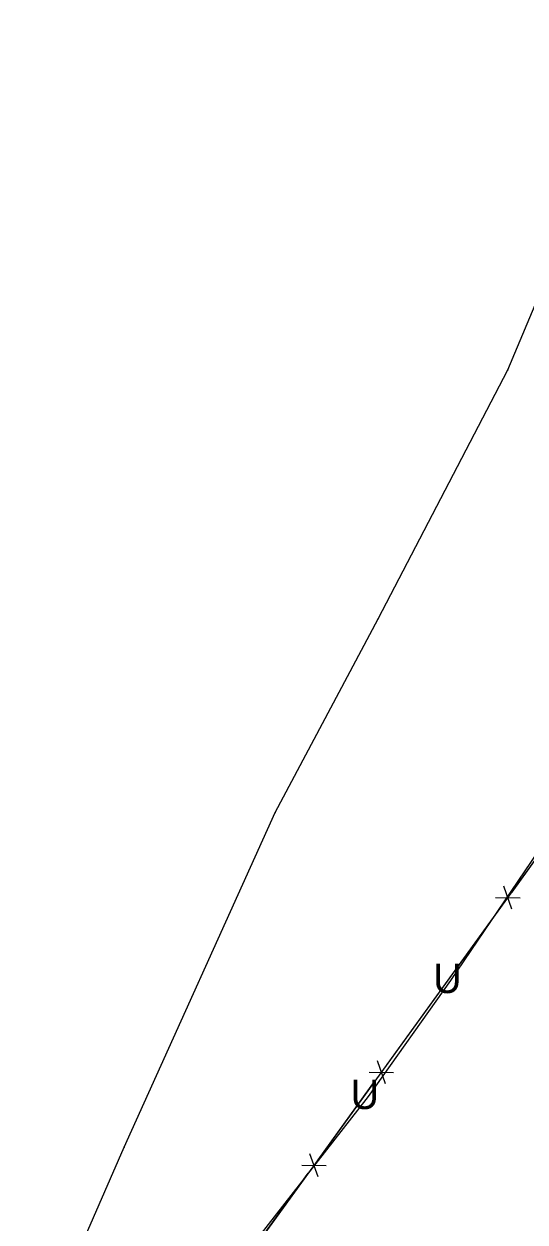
# Model space of a CAD drawing. Extents: x 1282810 to 1284464, y 402460 to 405899.
# Drawn here: x 1282963.2 to 1283065.5, y 403158.1 to 403402.5 of the extents above; entities that cross this region are included whole.
import ezdxf

# ---------------------------------------------------------------- set-up
doc = ezdxf.new("R2010")
doc.units = 0
for name, color, linetype in [('Default', 7, 'Continuous'), ('MOT_Proposed Road_Stage 2', 7, 'Continuous'), ('MOT_Shld_Stage 2', 7, 'Continuous'), ('S_FENCE', 7, 'Continuous'), ('S_UNDERGROUND_CABLE', 7, 'Continuous'), ('S_UTL_PT_SYM', 7, 'Continuous'), ('S_WATER_UTILITIES', 7, 'Continuous')]:
    doc.layers.add(name, color=color, linetype=linetype)

msp = doc.modelspace()

# ---------------------------------------------------------------- linework, layer by layer
at = {"layer": 'MOT_Proposed Road_Stage 2'}
msp.add_arc((1272453.81, 407390.3), 11435.16, 337.333333, 339.572534, dxfattribs=at)
at = {"layer": 'MOT_Shld_Stage 2'}
msp.add_arc((1272453.81, 407390.3), 11427.16, 337.333333, 339.572534, dxfattribs=at)
at = {"layer": 'S_FENCE'}
for p, q in [((1282983.71, 403116.17), (1283069.74, 403235)), ((1283059.46, 403224.28), (1283064.46, 403224.2)), ((1283062.77, 403221.88), (1283061.14, 403226.6)), ((1283036.97, 403186.24), (1283035.34, 403190.97)), ((1283033.65, 403188.64), (1283038.65, 403188.57)), ((1283023.23, 403167.26), (1283021.59, 403171.99)), ((1283019.91, 403169.66), (1283024.91, 403169.59))]:
    msp.add_line(p, q, dxfattribs=at)
for points in [[(1283062.8, 403225.4), (1283069.74, 403235)], [(1283037.33, 403190.22), (1283060.78, 403222.62)], [(1283023.25, 403170.79), (1283034.98, 403186.99)], [(1282997.78, 403135.61), (1283021.24, 403168.01)]]:
    msp.add_lwpolyline(points, dxfattribs=at)
at = {"layer": 'S_UNDERGROUND_CABLE'}
for p, q in [((1283050.34, 403207.32), (1283076.28, 403245.7)), ((1283033.51, 403183.66), (1283050.34, 403207.32)), ((1282997.54, 403137.63), (1283033.51, 403183.66))]:
    msp.add_line(p, q, dxfattribs=at)
at = {"layer": 'S_UTL_PT_SYM'}
for points in [[(1283061.96, 403331.96), (1283061.96, 403332.01), (1283061.96, 403331.96), (1283061.91, 403331.96), (1283061.96, 403331.96), (1283061.96, 403331.91), (1283061.96, 403331.96), (1283062.01, 403331.96)], [(1283035.52, 403281.16), (1283035.52, 403281.21), (1283035.52, 403281.16), (1283035.47, 403281.16), (1283035.52, 403281.16), (1283035.52, 403281.11), (1283035.52, 403281.16), (1283035.57, 403281.16)], [(1283014.52, 403241.63), (1283014.52, 403241.68), (1283014.52, 403241.63), (1283014.47, 403241.63), (1283014.52, 403241.63), (1283014.52, 403241.58), (1283014.52, 403241.63), (1283014.57, 403241.63)], [(1282983.72, 403173.33), (1282983.72, 403173.38), (1282983.72, 403173.33), (1282983.67, 403173.33), (1282983.72, 403173.33), (1282983.72, 403173.28), (1282983.72, 403173.33), (1282983.77, 403173.33)]]:
    msp.add_lwpolyline(points, dxfattribs=at)
at = {"layer": 'S_WATER_UTILITIES'}
for p, q in [((1283061.96, 403331.96), (1283091.5, 403402.51)), ((1283035.52, 403281.16), (1283061.96, 403331.96)), ((1283014.52, 403241.63), (1283035.52, 403281.16)), ((1282983.72, 403173.33), (1283014.52, 403241.63)), ((1282963.25, 403126.6), (1282983.72, 403173.33))]:
    msp.add_line(p, q, dxfattribs=at)

# ---------------------------------------------------------------- texts
at = {"layer": 'Default'}
for p in [(1283046.72, 403204.78), (1283029.88, 403181.12)]:
    msp.add_text('U', height=6, rotation=360, dxfattribs=at).set_placement(p)

doc.saveas('drawing.dxf')
